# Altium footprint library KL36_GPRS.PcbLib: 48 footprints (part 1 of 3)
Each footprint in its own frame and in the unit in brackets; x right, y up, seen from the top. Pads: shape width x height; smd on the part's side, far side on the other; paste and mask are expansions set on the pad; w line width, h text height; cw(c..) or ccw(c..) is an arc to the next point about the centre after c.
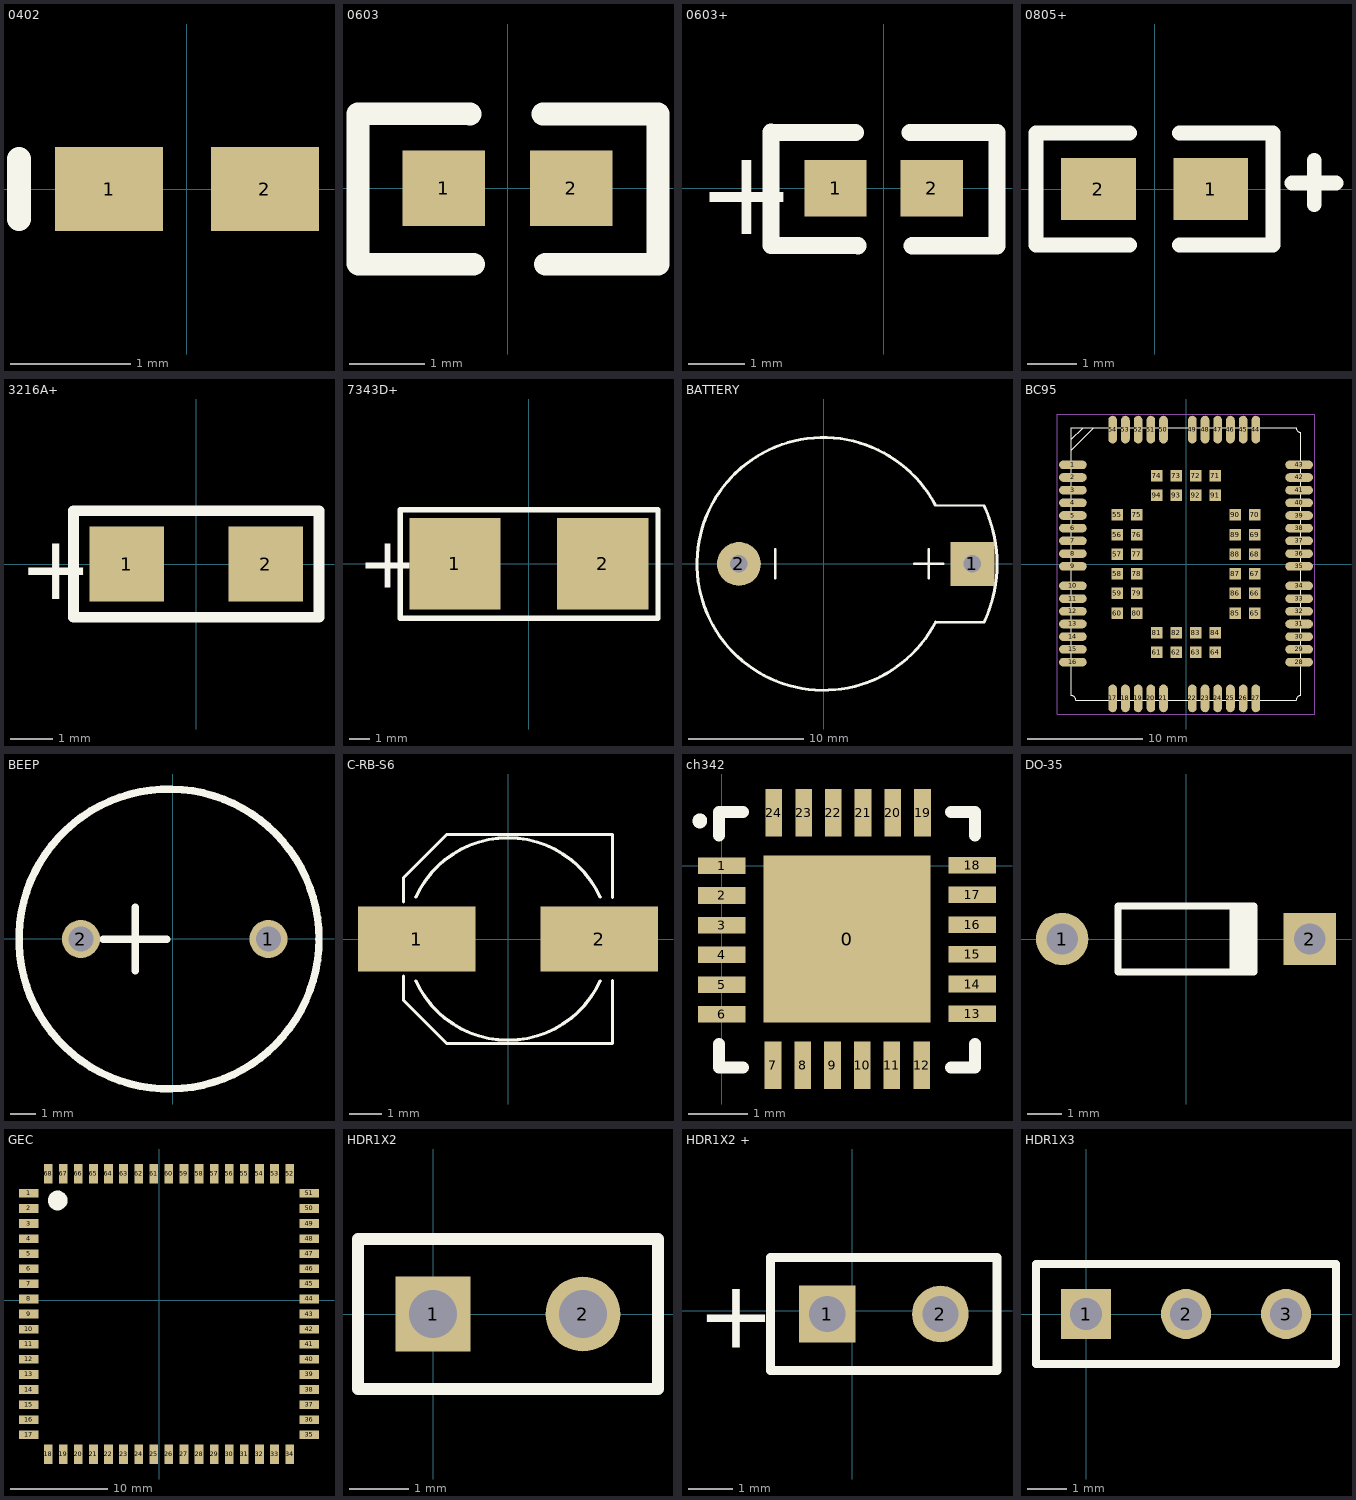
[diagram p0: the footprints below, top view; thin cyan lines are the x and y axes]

## 0402 [mm]
pads (2):
  rect 0.9x0.7 smd: 1(-0.65,0) 2(0.65,0)
Top Overlay:
  lines w0.2: -1.4,-0.25 -1.4,0.25

## 0603 [mm]
pads (2):
  rect 1.1x1 smd: 1(-0.85,0) 2(0.85,0)
Top Overlay:
  lines w0.305: -0.501,0.991 -1.992,0.992 -1.992,-1.004 -1.986,-1.01 -0.452,-1.012 ; 0.472,0.991 2.005,0.991 2.005,-1.012 0.505,-1.012

## 0603+ [mm]
pads (2):
  rect 1.1x1 smd: 1(-0.85,0) 2(0.85,0)
Top Overlay:
  lines w0.305: -0.501,0.991 -1.992,0.992 -1.992,-1.004 -1.986,-1.01 -0.452,-1.012 ; 0.472,0.991 2.005,0.991 2.005,-1.012 0.505,-1.012
  text "+" at -3.302,-0.813 h1.52

## 0805+ [mil]
pads (2):
  rect 60x50 smd: 1(45,0) 2(-45,0)
Top Overlay:
  lines w12: -20,-45 -95,-45 -95,45 -20,45 ; 20,-45 95,-45 95,45 20,45 ; 109.99,4.94 145.43,4.94 ; 128,-12.43 128,23

## 3216A+ [mil]
pads (2):
  rect 70x70 smd: 1(-65,0) 2(65,0)
Top Overlay:
  lines w10: -115,-50 -115,40 -115,50 115,50 115,-50 -115,-50
  text "+" at -166,-33 h60

## 7343D+ [mm]
height 3.1
pads (2):
  rect 4.5x4.5 smd: 1(-3.65,0) 2(3.65,0)
Top Overlay:
  lines w0.254: -6.35,-2.692 6.375,-2.692 6.375,2.667 -6.35,2.667 -6.35,-2.692
  text "+" at -8.433,-1.194 h2.54

## BATTERY [mil]
pads (2):
  rect 150x150 hole 60: 1(510,0)
  round 150 hole 60: 2(-290,0)
Top Overlay:
  lines w8: -165,-50 -165,50 ; 310,0 410,0 ; 360,-50 360,50 ; 382.44,200 550,200 ; 385,-200 545,-200 ; 390,-200 550,-200
  lines w10: 381.77,203.28 ccw(c-0.63,0) 383.81,-199.38 ; 550,-200 ccw(c121.82,-0.34) 550,199.32

## BC95 [mm]
pads (94):
  oval 2.4x0.75 smd: 1(-9.8,8.6) 2(-9.8,7.5) 3(-9.8,6.4) 4(-9.8,5.3) 5(-9.8,4.2) 6(-9.8,3.1) 7(-9.8,2) 8(-9.8,0.9) 9(-9.8,-0.2) 10(-9.8,-1.9) 11(-9.8,-3) 12(-9.8,-4.1) 13(-9.8,-5.2) 14(-9.8,-6.3) 15(-9.8,-7.4) 16(-9.8,-8.5) 28(9.8,-8.5) 29(9.8,-7.4) 30(9.8,-6.3) 31(9.8,-5.2) 32(9.8,-4.1) 33(9.8,-3) 34(9.8,-1.9) 35(9.8,-0.2) 36(9.8,0.9) 37(9.8,2) 38(9.8,3.1) 39(9.8,4.2) 40(9.8,5.3) 41(9.8,6.4) 42(9.8,7.5) 43(9.8,8.6)
  oval 0.75x2.4 smd: 17(-6.35,-11.65) 18(-5.25,-11.65) 19(-4.15,-11.65) 20(-3.05,-11.65) 21(-1.95,-11.65) 22(0.55,-11.65) 23(1.65,-11.65) 24(2.75,-11.65) 25(3.85,-11.65) 26(4.95,-11.65) 27(6.05,-11.65) 44(6.05,11.65) 45(4.95,11.65) 46(3.85,11.65) 47(2.75,11.65) 48(1.65,11.65) 49(0.55,11.65) 50(-1.95,11.65) 51(-3.05,11.65) 52(-4.15,11.65) 53(-5.25,11.65) 54(-6.35,11.65)
  rect 1x1 smd: 55(-5.95,4.25) 56(-5.95,2.55) 57(-5.95,0.85) 58(-5.95,-0.85) 59(-5.95,-2.55) 60(-5.95,-4.25) 61(-2.55,-7.65) 62(-0.85,-7.65) 63(0.85,-7.65) 64(2.55,-7.65) 65(5.95,-4.25) 66(5.95,-2.55) 67(5.95,-0.85) 68(5.95,0.85) 69(5.95,2.55) 70(5.95,4.25) 71(2.55,7.65) 72(0.85,7.65) 73(-0.85,7.65) 74(-2.55,7.65) 75(-4.25,4.25) 76(-4.25,2.55) 77(-4.25,0.85) 78(-4.25,-0.85) 79(-4.25,-2.55) 80(-4.25,-4.25) 81(-2.55,-5.95) 82(-0.85,-5.95) 83(0.85,-5.95) 84(2.55,-5.95) 85(4.25,-4.25) 86(4.25,-2.55) 87(4.25,-0.85) 88(4.25,0.85) 89(4.25,2.55) 90(4.25,4.25) 91(2.55,5.95) 92(0.85,5.95) 93(-0.85,5.95) 94(-2.55,5.95)
Top Overlay:
  lines w0.1: -9.95,9.851 -8.001,11.8 -9.271,11.8 ; -9.95,10.033 -9.95,11.375 ; -9.95,10.414 -9.95,11.8 ; -9.931,10.82 -8.966,11.786 ; -8.437,11.8 -9.95,11.8 ; -9.95,11.8 -9.95,-11.4 cw(c-9.95,-11.8) -9.55,-11.8 9.55,-11.8 cw(c9.95,-11.8) 9.95,-11.4 9.95,11.4 cw(c9.95,11.8) 9.55,11.8 -9.95,11.8
Mechanical 1:
  lines w0.01: -11.15,-13 11.15,-13 11.15,13 -11.15,13 -11.15,-13

## BEEP [mil]
pads (2):
  round 60 hole 39.37: 1(150.33,-0.31) 2(-144.95,-0.31)
Top Overlay:
  circle w11.81: c-6.17,-0.31 r236.22
  lines w11.81: -109.67,-0.31 -9.67,-0.31 ; -59.67,-50.31 -59.67,49.69

## C-RB-S6 [mm]
pads (2):
  rect 3.6x2 smd: 1(-2.794,0) 2(2.794,0)
Top Overlay:
  lines w0.1: -3.2,-1.143 -3.2,-1.88 -1.88,-3.2 3.2,-3.2 3.2,-1.27 ; -3.2,1.143 -3.2,1.88 -1.88,3.2 3.2,3.2 3.2,1.27 ; -2.822,-1.283 ccw(c0,0) 2.822,-1.283 ; -2.822,1.283 cw(c0,0) 2.822,1.283

## ch342 [mm]
pads (25):
  rect 2.8x2.8 smd: 0(2.108,-1.232)
  rect 0.8x0.28 smd: 1(0,0) 2(0,-0.5) 3(0,-1.001) 4(0,-1.499) 5(0,-1.999) 6(0,-2.499) 13(4.216,-2.489) 14(4.216,-1.989) 15(4.216,-1.488) 16(4.216,-0.991) 17(4.216,-0.49) 18(4.216,0.01)
  rect 0.28x0.8 smd: 7(0.864,-3.353) 8(1.364,-3.353) 9(1.864,-3.353) 10(2.362,-3.353) 11(2.863,-3.353) 12(3.363,-3.353) 19(3.378,0.889) 20(2.878,0.889) 21(2.377,0.889) 22(1.88,0.889) 23(1.379,0.889) 24(0.879,0.889)
Top Overlay:
  circle w0.25: c-0.366,0.754 r0
  lines w0.2: -0.042,-2.995 -0.042,-3.395 0.358,-3.395 ; -0.042,0.505 -0.042,0.906 0.358,0.906 ; 3.858,-3.395 4.258,-3.395 4.258,-2.995 ; 3.858,0.906 4.258,0.906 4.258,0.505

## DO-35 [mm]
pads (2):
  round 1.5 hole 0.9: 1(-3.55,0)
  rect 1.5x1.5 hole 0.9: 2(3.55,0)
Top Overlay:
  rectangle: 1.25,-0.95 2.05,0.95
  lines w0.2: 1.95,-0.95 -1.95,-0.95 -1.95,0.95 1.95,0.95

## GEC [mm]
pads (68):
  rect 2x0.9 smd: 1(-13.513,11.049) 2(-13.513,9.489) 3(-13.513,7.929) 4(-13.513,6.369) 5(-13.513,4.809) 6(-13.513,3.249) 7(-13.513,1.689) 8(-13.513,0.129) 9(-13.513,-1.431) 10(-13.513,-2.991) 11(-13.513,-4.551) 12(-13.513,-6.111) 13(-13.513,-7.671) 14(-13.513,-9.231) 15(-13.513,-10.791) 16(-13.513,-12.351) 17(-13.513,-13.911) 35(15.487,-13.911) 36(15.487,-12.351) 37(15.487,-10.791) 38(15.487,-9.231) 39(15.487,-7.671) 40(15.487,-6.111) 41(15.487,-4.551) 42(15.487,-2.991) 43(15.487,-1.431) 44(15.487,0.129) 45(15.487,1.689) 46(15.487,3.249) 47(15.487,4.809) 48(15.487,6.369) 49(15.487,7.929) 50(15.487,9.489) 51(15.487,11.049)
  rect 0.9x2 smd: 18(-11.506,-15.926) 19(-9.946,-15.926) 20(-8.386,-15.926) 21(-6.826,-15.926) 22(-5.266,-15.926) 23(-3.706,-15.926) 24(-2.146,-15.926) 25(-0.586,-15.926) 26(0.974,-15.926) 27(2.534,-15.926) 28(4.094,-15.926) 29(5.654,-15.926) 30(7.214,-15.926) 31(8.774,-15.926) 32(10.334,-15.926) 33(11.894,-15.926) 34(13.454,-15.926) 52(13.454,13.081) 53(11.894,13.081) 54(10.334,13.081) 55(8.774,13.081) 56(7.214,13.081) 57(5.654,13.081) 58(4.094,13.081) 59(2.534,13.081) 60(0.974,13.081) 61(-0.586,13.081) 62(-2.146,13.081) 63(-3.706,13.081) 64(-5.266,13.081) 65(-6.826,13.081) 66(-8.386,13.081) 67(-9.946,13.081) 68(-11.506,13.081)
Top Overlay:
  circle w1.016: c-10.516,10.312 r0.508

## HDR1X2 [mil]
pads (2):
  rect 50x50 hole 32: 1(0,0)
  round 50 hole 32: 2(100,0)
Top Overlay:
  lines w7.87: -50,-50 -50,50 150,50 150,-50 -50,-50

## HDR1X2 + [mil]
pads (2):
  rect 50x50 hole 32: 1(-22,-3)
  round 50 hole 32: 2(78,-3)
Top Overlay:
  lines w7.87: -72,-53 -72,47 128,47 128,-53 -72,-53
  text "+" at -137,-33 h60

## HDR1X3 [mil]
pads (3):
  rect 50x50 hole 32: 1(0,0)
  round 50 hole 32: 2(100,0) 3(200,0)
Top Overlay:
  lines w7.87: -50,-50 -50,50 250,50 250,-50 -50,-50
